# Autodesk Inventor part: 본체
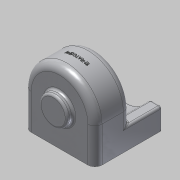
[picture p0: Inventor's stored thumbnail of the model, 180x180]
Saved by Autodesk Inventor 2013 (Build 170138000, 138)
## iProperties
Created: 2015-02
Part Number: 본체
Material: 알루미늄 6061
Document SubType Name: Modeling
Designer: Administrator
Density: 1 g/cm^3
Author: Administrator
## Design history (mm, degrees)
sketch "스케치1"
  geometry: L1 (-50, -50)-(50, -50); L2 (-50, -50)-(-50, 0); L3 (50, -50)-(50, 0); A1 r 50 centre (0, 0) between (-50, 0) and (50, 0); 2 further points
  constraints: 6 end point, 2 point on circle, 2 tangent, 1 centre point, 1 coincident, 1 horizontal, 1 midpoint, 1 vertical alignment
  dimensions: "d0" = 100 diameter of A1; "d1" = 100 distance of L1.start L1.end; "d2" = 50 distance from line of L1 point (0, 0)
extrude "돌출1" new body sketch "스케치1" distance "d3" = 95; taper "d4" = 0 deg
sketch "스케치2"
  geometry: L1 (50, 50)-(-50, 50) reference; L2 (-50, 50)-(-50, 0) reference; L3 (50, 0)-(50, 50) reference; L4 (50, 50)-(-50, 50); L5 (-50, 50)-(-50, 20); L6 (-50, 20)-(50, 20); L7 (50, 20)-(50, 50); L8 (50, 20)-(50, 0); L9 (-50, 20)-(-50, 0); C1 r 40 at (0, 0); C2 r 50 at (0, 0); A1 r 50 centre (0, 0) between (-50, 0) and (50, 0) reference
  constraints: 12 end point, 2 centre point, 2 coincident, 2 parallel, 2 tangent, 1 collinear, 1 horizontal, 1 perpendicular, 1 point on line
  dimensions: "d5" = 80 diameter of C1; "d6" = 30 distance of L5.end L4.end; "d7" = 100 diameter of C2
extrude "돌출2" cut sketch "스케치2" distance "d8" = 45; taper "d9" = 0 deg
sketch "스케치3"
  geometry: C1 r 20 at (0, 0); A1 r 50 centre (0, 0) between (50, 0) and (-50, 0) reference
  constraints: 1 centre point, 1 coincident
  dimensions: "d10" = 40 diameter of C1
extrude "돌출3" join sketch "스케치3" distance "d11" = 9; taper "d12" = 0 deg
sketch "스케치4"
  geometry: C1 r 25 at (0, 0); A1 r 50 centre (0, 0) between (-50, 0) and (50, 0) reference
  constraints: 1 centre point, 1 coincident
  dimensions: "d13" = 50 diameter of C1
extrude "돌출4" join sketch "스케치4" distance "d14" = 10; taper "d15" = 0 deg
feature "면 기울기1" dims angle "d16" = 20 deg
node "작업 평면1"
sketch "스케치5" dims "d17" = 92
  geometry: L1 (50, 50)-(50, 0) reference; L2 (-50, 0)-(-50, 50) reference; L3 (-50, 50)-(50, 50) reference; L4 (46, 50)-(-46, 50); L5 (-46, 50)-(-46, 0); L6 (-46, 0)-(46, 0); L7 (46, 0)-(46, 50); A1 r 50 centre (0, 0) between (-50, 0) and (50, 0) reference; 3 further points
  constraints: 8 end point, 2 coincident, 2 parallel, 1 horizontal, 1 horizontal alignment, 1 midpoint, 1 perpendicular, 1 point on line, 2 other
extrude "돌출5" cut sketch "스케치5" stored distance "d18" = 42; taper "d19" = 0 deg
hole "구멍1" diameter "d22" = 28; stored, may be unused: countersink angle "d26" = 90 deg, drill point angle "d28" = 0 deg; dims "d20" = 10, "d21" = 10, "d23" = 6, "d24" = 4, "d25" = 2, "d27" = 10
hole "구멍2" diameter "d31" = 20; stored, may be unused: countersink angle "d35" = 90 deg, drill point angle "d37" = 0 deg; dims "d29" = 10, "d30" = 10, "d32" = 6, "d33" = 4, "d34" = 2, "d36" = 4
hole "구멍3" diameter "d40" = 28; stored, may be unused: countersink angle "d44" = 90 deg, drill point angle "d46" = 0 deg; dims "d38" = 10, "d39" = 10, "d41" = 6, "d42" = 4, "d43" = 2, "d45" = 8
hole "구멍4" diameter "d49" = 20; stored, may be unused: countersink angle "d53" = 90 deg, drill point angle "d55" = 0 deg; dims "d47" = 10, "d48" = 10, "d50" = 6, "d51" = 4, "d52" = 2, "d54" = 2
sketch "스케치6"
  geometry: C1 r 14 at (0, 0) reference; 1 further point
  constraints: 1 vertical alignment
  dimensions: "d56" = 18 distance of C1.centre point (0, -18)
hole "구멍5" sketch "스케치6" at (0, -18) diameter "d57" = 2.459; stored, may be unused: countersink angle "d61" = 90 deg, drill point angle "d63" = 118 deg; dims "d58" = 6, "d59" = 4, "d60" = 2, "d62" = 9
fillet "모깎기1" dims "d67" = 10
fillet "모깎기2" dims "d68" = 6
chamfer "모따기1" distance "d69" = 1; stored, may be unused: second distance "d70" = 2, angle "d71" = 45 deg
chamfer "모따기2" distance "d72" = 1; stored, may be unused: second distance "d73" = 2, angle "d74" = 45 deg
fillet "모깎기3" dims "d75" = 0.3
fillet "모깎기4" dims "d76" = 0.3
fillet "모깎기5" dims "d77" = 3
fillet "모깎기6" dims "d78" = 3
fillet "모깎기7" dims "d79" = 3
sketch "스케치7"
  geometry: L1 (90, 10)-(90, 92) reference; L2 (-7, 95)-(87, 95) reference; 5 further points
  constraints: 2 horizontal alignment, 2 vertical alignment
  dimensions: "d80" = 33 distance of point (81.75, 53) point (81.75, 86); "d82" = 83.5 distance of point (-1.75, 86) point (81.75, 86); "d83" = 8.25 distance from line of L1 point (81.75, 86); "d84" = 9 distance from line of L2 point (-1.75, 86)
hole "구멍6" sketch "스케치7" at (-1.75, 86), (-1.75, 53), (81.75, 86), (81.75, 53) diameter "d85" = 5.134; stored, may be unused: countersink angle "d89" = 90 deg, drill point angle "d91" = 118 deg; dims "d86" = 10, "d87" = 4, "d88" = 2, "d90" = 13
node "작업 평면2"
sketch "스케치8"
  geometry: 2 further points
  constraints: 1 vertical alignment, 1 other
  dimensions: "d92" = 25 distance of point (0, 25) point (0, 0)
feature "엠보싱1" sketch "스케치8" dims "d0" = 100, "d1" = 100, "d2" = 50, "d93" = 0.5, "d94" = 0
fillet "모깎기8" dims "d95" = 3
node "솔리드1"
pattern_circular "원형 패턴1" dims angle "d65" = 360 deg
node "절단 모서리 투영1"
